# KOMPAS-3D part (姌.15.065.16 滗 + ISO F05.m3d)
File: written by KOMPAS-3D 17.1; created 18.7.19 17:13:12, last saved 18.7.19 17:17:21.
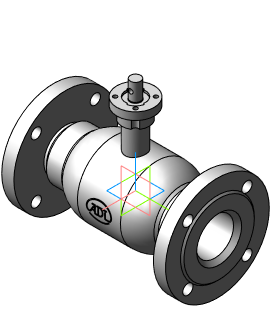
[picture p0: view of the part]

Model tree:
1. Операция без истории:3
